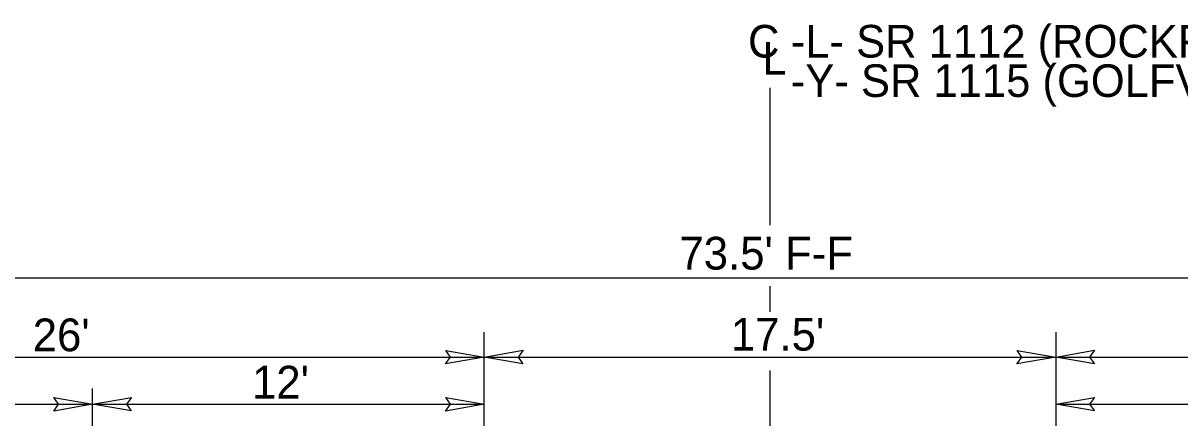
# Model space of a CAD drawing. Extents: x 958711 to 962106, y 831169 to 840840.
# Drawn here: x 961244.1 to 961520, y 838741.4 to 838835.4 of the extents above; entities that cross this region are included whole.
import ezdxf

# ---------------------------------------------------------------- set-up
doc = ezdxf.new("R2010")
doc.units = 0
for name, color, linetype in [('Default', 7, 'Continuous'), ('Old_Level_1', 7, 'Continuous'), ('Prop Dimension Text', 7, 'Continuous'), ('Typical Terminator CELL', 7, 'Continuous')]:
    doc.layers.add(name, color=color, linetype=linetype)

msp = doc.modelspace()

# ---------------------------------------------------------------- linework, layer by layer
at = {"layer": 'Default'}
for p, q in [((961422.25, 838820.03), (961422.25, 838787.31)), ((961422.25, 838772.82), (961422.25, 838766.68)), ((961422.25, 838752.71), (961422.25, 838653.62))]:
    msp.add_line(p, q, dxfattribs=at)
at = {"layer": 'Old_Level_1'}
for p, q in [((961140.72, 838774.8), (961707.16, 838774.8)), ((961354.09, 838671.12), (961354.09, 838761.83)), ((961490.42, 838761.83), (961490.42, 838670.97)), ((961153.92, 838755.91), (961354.09, 838755.91)), ((961354.09, 838755.91), (961490.42, 838755.91)), ((961490.42, 838755.91), (961693.95, 838755.91)), ((961260.61, 838668.89), (961260.61, 838748.41)), ((961153.92, 838744.66), (961260.61, 838744.66)), ((961260.61, 838744.66), (961354.09, 838744.66)), ((961490.42, 838744.66), (961583.9, 838744.66))]:
    msp.add_line(p, q, dxfattribs=at)
at = {"layer": 'Typical Terminator CELL'}
for points in [[(961344.87, 838757.5), (961354.09, 838755.91), (961344.82, 838754.27), (961346, 838755.91)], [(961363.31, 838754.32), (961354.09, 838755.91), (961363.37, 838757.55), (961362.19, 838755.91)], [(961481.19, 838757.5), (961490.42, 838755.91), (961481.14, 838754.27), (961482.32, 838755.91)], [(961499.64, 838754.32), (961490.42, 838755.91), (961499.69, 838757.55), (961498.51, 838755.91)], [(961251.39, 838746.25), (961260.61, 838744.66), (961251.34, 838743.02), (961252.52, 838744.66)], [(961269.83, 838743.08), (961260.61, 838744.66), (961269.89, 838746.3), (961268.71, 838744.66)], [(961344.87, 838746.25), (961354.09, 838744.66), (961344.82, 838743.02), (961346, 838744.66)], [(961499.64, 838743.08), (961490.42, 838744.66), (961499.69, 838746.3), (961498.51, 838744.66)]]:
    msp.add_lwpolyline(points, close=True, dxfattribs=at)

# ---------------------------------------------------------------- texts
at = {"layer": 'Prop Dimension Text'}
for s, height, p in [('C', 7.77, (961417.01, 838827.25)), ('-L- SR 1112 (ROCKFISH ROAD)', 7.7675, (961427.22, 838827.26)), ('L', 7.77, (961420.41, 838823.16)), ('-Y- SR 1115 (GOLFVIEW ROAD)', 7.7675, (961427.22, 838817.87)), ("73.5' F-F", 7.801, (961400.64, 838776.75)), ("26'", 7.801, (961246.34, 838757.29)), ("17.5'", 7.801, (961412.91, 838757.44)), ("12'", 7.801, (961298.66, 838746.04))]:
    msp.add_text(s, height=height, rotation=0, dxfattribs=at).set_placement(p)

doc.saveas('drawing.dxf')
